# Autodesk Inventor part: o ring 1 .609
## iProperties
Created: 2007-11
Part Number: o ring 1 .609
Document SubType Name: Modeling
Designer: lwoods
Density: 1 g/cm^3
Author: lwoods
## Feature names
1. Revolution1
